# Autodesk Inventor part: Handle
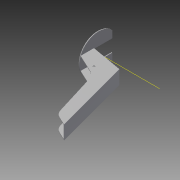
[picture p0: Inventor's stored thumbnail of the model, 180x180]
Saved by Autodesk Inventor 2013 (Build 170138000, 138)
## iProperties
Created: 2009-03
Part Number: Handle
Document SubType Name: Modeling
Designer: tangg
Density: 7.85 g/cm^3
Material: Steel
Mass: 68.364 g
Surface Area: 180.393 cm^2
Volume: 8.70879 cm^3
Author: tangg
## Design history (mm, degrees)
sketch "Sketch1"
  geometry: L1 (0, -11.392)-(0, 0); L2 (35.824, -35.395)-(54.061, -95.007); L3 (0, -11.392)-(25.151, -23.12); L4 (62.066, -104.214)-(74.474, -110); L5 (74.474, -110)-(45, 0); L6 (0, 0)-(40.182, 0); L7 (0, 0)-(45, 0); L8 (45, 0)-(0, 8); L9 (0, 8)-(0, 0); L10 (27.142, 13.608)-(-2.758, 13.608) reference; A1 r 20 centre (16.699, -41.246) between (35.824, -35.395) and (25.151, -23.12); A2 r 15 centre (68.405, -90.619) between (54.061, -95.007) and (62.066, -104.214); 4 further points
  constraints: 20 end point, 4 point on circle, 4 point on line, 4 tangent, 2 centre point, 2 horizontal, 1 coincident, 1 parallel, 1 perpendicular, 1 vertical, 2 other
  dimensions: "d6" = 20 radius of A1; "d9" = 110 vertical distance of L4.end L5.end; "d10" = 15 radius of A2; "d11" = 105 deg angle of L5 L6; "d13" = 115 deg angle of L3 L1; "d14" = 45 distance of point (0, 0) L5.end; "d15" = 8 distance of L8.end point (0, 0); "d18" = 5.60779 distance from line of L8.end L10; "d19" = 25 distance from line of L1.start L10; "d29" = 15 vertical distance of point (23, -15) point (0, 0); "d30" = 23 horizontal distance of point (0, 0) point (23, -15)
extrude "Extrusion2" new body sketch "Sketch1" stored distance "d3" = 20; taper "d4" = 0 deg
fillet "Fillet1" dims "d25" = 2
shell "Shell2" dims "d5" = 1
sketch "Sketch2"
  geometry: L1 (-9.708, 3.608)-(-10.292, 3.608); L2 (-20, 19.392)-(-19, 19.392) reference; L3 (-20, 0)-(-19, 0) reference; L4 (-29.391, 46)-(-19, 46); L5 (-1, 1)-(-1, 19.392); L6 (-19, 1)-(-19, 5.494); L7 (-1, 46)-(9.391, 46); L8 (-19, 46)-(-1, 46); L9 (-20, 19.392)-(-20, 0) reference; L10 (-19, 19.392)-(-1, 19.392); L11 (-19, 19.392)-(-19, 46); L12 (-1, 19.392)-(-1, 46); L13 (-19, 5.494)-(-19, 19.392); L14 (-16, 19.392)-(-4, 19.392); L15 (-4, 19.392)-(-4, 9.392); L16 (-16, 9.392)-(-16, 19.392); L17 (-19, 0)-(-19, 19.392) reference; A1 r 22.394 centre (-10, 26) between (-10.292, 3.608) and (-9.708, 3.608); A2 r 27.857 centre (-10, 26) between (-29.391, 46) and (9.391, 46); A3 r 9 centre (-10, 19.392) between (-19, 19.392) and (-1, 19.392); 4 further points
  constraints: 27 end point, 17 perpendicular, 8 point on circle, 4 parallel, 3 centre point, 3 coincident, 2 midpoint, 1 horizontal, 1 point on line, 1 other
  dimensions: "d21" = 25 vertical distance of L5.start point (-10, 26); "d26" = 20 distance from line of L4 A1.centre; "d27" = 12 distance between parallel lines of L15 L16
extrude "Extrusion3" join sketch "Sketch2" distance "d7" = 1; taper "d8" = 0 deg
workaxis "Work Axis1"
sketch "Sketch3"
  geometry: C1 r 1.5 at (23, -15); 2 further points
  constraints: 1 centre point, 1 coincident
  dimensions: "d31" = 3 diameter of C1
extrude "Extrusion4" cut sketch "Sketch3" stored distance "d32" = 10; taper "d33" = 0 deg
body "Solid2"
